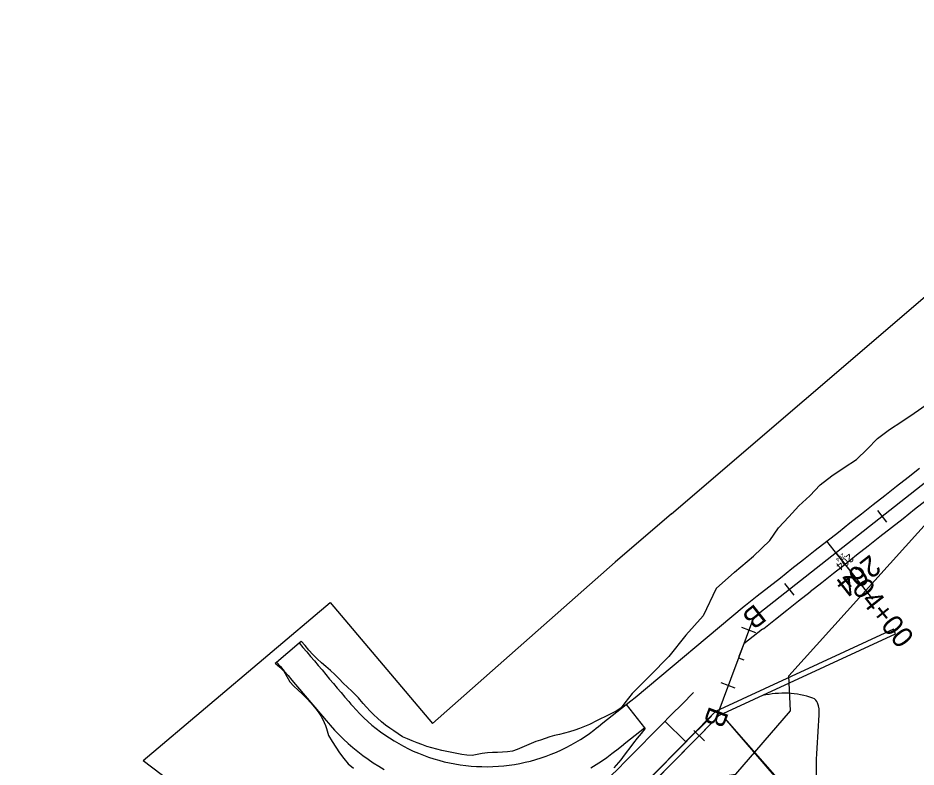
# Model space of a CAD drawing. Extents: x 1823824 to 1861612, y 706975 to 726130.
# Drawn here: x 1824837.5 to 1825141.5, y 712255.1 to 712508.6 of the extents above; entities that cross this region are included whole.
import ezdxf

# ---------------------------------------------------------------- set-up
doc = ezdxf.new("R2010")
doc.units = 0
for name, color, linetype in [('DR_X_Flood_Boundary', 7, 'Continuous'), ('GE_X_CL_10', 7, 'Continuous'), ('GE_X_CL_100', 7, 'Continuous'), ('GE_X_CL_20', 7, 'Continuous'), ('GE_X_CL_200', 7, 'Continuous'), ('GE_X_CL_50', 7, 'Continuous'), ('RW_X_Esmt_FL', 7, 'Continuous'), ('SC_Scratch1', 7, 'Continuous'), ('SC_Scratch2', 7, 'Continuous'), ('SC_Scratch3', 7, 'Continuous'), ('SC_Scratch5', 7, 'Continuous'), ('SC_Scratch6', 7, 'Continuous')]:
    doc.layers.add(name, color=color, linetype=linetype)

msp = doc.modelspace()

# ---------------------------------------------------------------- linework, layer by layer
at = {"layer": 'DR_X_Flood_Boundary'}
for p, q in [((1825243.83, 712429.46), (1825086.51, 712305.67)), ((1825086.51, 712305.67), (1825073.72, 712271.49)), ((1825073.72, 712271.49), (1825010.26, 712206.92))]:
    msp.add_line(p, q, dxfattribs=at)
at = {"layer": 'GE_X_CL_10'}
for p, q in [((1825114.42, 712327.63), (1825115.03, 712326.84)), ((1825081.43, 712292.1), (1825082.37, 712291.75))]:
    msp.add_line(p, q, dxfattribs=at)
at = {"layer": 'GE_X_CL_100'}
msp.add_line((1825114.42, 712327.63), (1825120.6, 712319.77), dxfattribs=at)
at = {"layer": 'GE_X_CL_20'}
for p, q in [((1825114.42, 712327.63), (1825115.65, 712326.06)), ((1825081.43, 712292.1), (1825083.3, 712291.4))]:
    msp.add_line(p, q, dxfattribs=at)
at = {"layer": 'GE_X_CL_200'}
msp.add_line((1825114.42, 712327.63), (1825126.78, 712311.91), dxfattribs=at)
at = {"layer": 'GE_X_CL_50'}
msp.add_line((1825114.42, 712327.63), (1825117.51, 712323.7), dxfattribs=at)
at = {"layer": 'RW_X_Esmt_FL'}
for p, q in [((1825058.79, 712340.8), (1825254.52, 712508.57)), ((1825058.79, 712340.8), (1825039.75, 712324.4)), ((1824977.83, 712269.92), (1825039.75, 712324.4)), ((1824879.92, 712257.3), (1824943.2, 712310.84)), ((1824943.2, 712310.84), (1824977.83, 712269.92)), ((1824879.92, 712257.3), (1824889.34, 712250.21))]:
    msp.add_line(p, q, dxfattribs=at)
at = {"layer": 'SC_Scratch1'}
for p, q in [((1825073.85, 712315.5), (1825080.12, 712321.03)), ((1825046.47, 712278.7), (1825083.42, 712309.6)), ((1825089.6, 712301.74), (1825083.21, 712296.86)), ((1825083.21, 712296.86), (1825081.59, 712292.52)), ((1825076.76, 712271.73), (1825133.34, 712206.03))]:
    msp.add_line(p, q, dxfattribs=at)
for points in [[(1824837.54, 711922.74), (1824848.43, 711918.74), (1824860.1, 711923.16), (1824873.6, 711947.64), (1824870.6, 711959.21), (1824893.22, 711999.63), (1824920.18, 712044.82), (1824961.46, 712108.81), (1824989.89, 712150.42), (1824991.25, 712152.45), (1825003.05, 712154.01), (1825020.13, 712176.93), (1825019.11, 712188.57), (1825068.43, 712250.92), (1825080.52, 712252.77), (1825099.08, 712274.14), (1825098.5, 712286.03), (1825161.91, 712356.25)], [(1824837.54, 711922.74), (1824848.43, 711918.74), (1824860.1, 711923.16), (1824873.6, 711947.64), (1824870.6, 711959.21), (1824893.22, 711999.63), (1824920.18, 712044.82), (1824961.46, 712108.81), (1824989.89, 712150.42), (1824991.25, 712152.45), (1825003.05, 712154.01), (1825020.13, 712176.93), (1825019.11, 712188.57), (1825068.43, 712250.92), (1825080.52, 712252.77), (1825099.08, 712274.14), (1825098.5, 712286.03), (1825161.91, 712356.25)], [(1825080.12, 712321.03), (1825086.51, 712326.48), (1825092.08, 712331.76)], [(1825083.42, 712309.6), (1825083.82, 712309.91), (1825087.75, 712313.01), (1825091.68, 712316.1), (1825095.61, 712319.19), (1825099.53, 712322.28), (1825099.53, 712322.28)], [(1825073.85, 712315.5), (1825069.48, 712306.35), (1825063.64, 712299.71), (1825057.83, 712292.56), (1825051.5, 712286.15), (1825047.36, 712281.96), (1825045.42, 712280.04)], [(1825089.6, 712301.74), (1825090, 712302.05), (1825093.93, 712305.15), (1825097.86, 712308.24), (1825101.79, 712311.33), (1825105.72, 712314.42), (1825105.72, 712314.42)], [(1824924.59, 712290.24), (1824925.07, 712290.65), (1824932.7, 712297.12), (1824933.43, 712297.74)], [(1824932.7, 712297.12), (1824933.99, 712295.6), (1824935.29, 712294.07), (1824936.58, 712292.55), (1824937.87, 712291.02), (1824939.17, 712289.5), (1824940.46, 712287.97), (1824941.76, 712286.45), (1824943.05, 712284.92), (1824944.34, 712283.4), (1824945.64, 712281.87), (1824946.93, 712280.35), (1824948.23, 712278.82), (1824949.52, 712277.3), (1824950.25, 712276.44), (1824950.78, 712275.83), (1824952.01, 712274.46), (1824953.29, 712273.12), (1824954.6, 712271.83), (1824955.96, 712270.57), (1824957.35, 712269.36), (1824958.78, 712268.2), (1824960.25, 712267.07), (1824961.75, 712266), (1824963.28, 712264.97), (1824964.84, 712263.98), (1824966.43, 712263.05), (1824968.05, 712262.16), (1824969.7, 712261.33), (1824971.37, 712260.54), (1824973.07, 712259.81), (1824974.78, 712259.13), (1824976.52, 712258.51), (1824978.27, 712257.93), (1824980.05, 712257.42), (1824981.83, 712256.95), (1824983.63, 712256.54), (1824985.45, 712256.19), (1824987.27, 712255.89), (1824989.1, 712255.65), (1824990.93, 712255.47), (1824992.78, 712255.34), (1824994.62, 712255.27), (1824996.47, 712255.26), (1824998.31, 712255.3), (1825000.16, 712255.4), (1825002, 712255.56), (1825003.83, 712255.77), (1825005.66, 712256.04), (1825007.47, 712256.36), (1825009.28, 712256.74), (1825011.07, 712257.18), (1825012.85, 712257.67), (1825014.62, 712258.22), (1825016.36, 712258.82), (1825018.09, 712259.47), (1825019.79, 712260.17), (1825021.48, 712260.93), (1825023.14, 712261.74), (1825024.77, 712262.6), (1825026.38, 712263.51), (1825027.95, 712264.47), (1825029.5, 712265.48), (1825031.02, 712266.53), (1825032.5, 712267.63), (1825033.28, 712268.24), (1825034.01, 712268.82), (1825035.57, 712270.06), (1825037.14, 712271.3), (1825038.71, 712272.54), (1825040.28, 712273.79), (1825041.84, 712275.03), (1825043.41, 712276.27), (1825044.98, 712277.51), (1825046.47, 712278.7)], [(1825045.42, 712280.04), (1825044.22, 712278.47), (1825042.98, 712276.82), (1825041.75, 712275.15), (1825040.09, 712274.02), (1825038.25, 712273.13), (1825036.39, 712272.25), (1825034.54, 712271.37), (1825032.74, 712270.42), (1825031.9, 712269.98), (1825031.02, 712269.56), (1825029.36, 712268.83), (1825027.68, 712268.19), (1825025.99, 712267.6), (1825024.29, 712267.06), (1825022.6, 712266.58), (1825020.9, 712266.15), (1825019.21, 712265.78), (1825017.54, 712265.39), (1825015.97, 712264.82), (1825014.4, 712264.26), (1825012.81, 712263.74), (1825011.27, 712263.08), (1825009.72, 712262.39), (1825008.15, 712261.72), (1825006.56, 712261.07), (1825004.93, 712260.48), (1825003.23, 712260.33), (1825001.53, 712260.21), (1824999.83, 712260.11), (1824998.13, 712260.02), (1824996.43, 712259.96), (1824994.72, 712259.67), (1824992.99, 712259.33), (1824991.24, 712259.02), (1824989.5, 712259.16), (1824987.78, 712259.41), (1824986.07, 712259.7), (1824984.36, 712260.02), (1824982.66, 712260.37), (1824980.97, 712260.76), (1824979.28, 712261.18), (1824977.59, 712261.63), (1824975.91, 712262.12), (1824974.27, 712262.71), (1824972.62, 712263.33), (1824970.99, 712263.98), (1824969.37, 712264.67), (1824967.76, 712265.39), (1824966.27, 712266.34), (1824964.82, 712267.34), (1824963.38, 712268.34), (1824961.95, 712269.36), (1824960.57, 712270.46), (1824959.26, 712271.63), (1824957.99, 712272.84), (1824956.76, 712274.09), (1824955.56, 712275.37), (1824954.41, 712276.68), (1824953.27, 712278), (1824952.76, 712278.56), (1824951.98, 712279.39), (1824950.6, 712280.84), (1824949.1, 712282.18), (1824947.61, 712283.54), (1824946.22, 712284.99), (1824944.83, 712286.43), (1824943.32, 712287.78), (1824941.8, 712289.11), (1824940.29, 712290.45), (1824938.78, 712291.79), (1824937.35, 712293.2), (1824935.95, 712294.64), (1824934.71, 712296.21), (1824933.43, 712297.74)], [(1824924.59, 712290.24), (1824926.18, 712288.97), (1824927.56, 712287.52), (1824928.59, 712285.77), (1824929.62, 712284.02), (1824930.97, 712282.54), (1824932.41, 712281.14), (1824933.86, 712279.75), (1824935.28, 712278.33), (1824936.69, 712276.91), (1824937.95, 712275.35), (1824939.17, 712273.76), (1824940.33, 712272.13), (1824941.14, 712270.18), (1824941.67, 712269.15), (1824941.99, 712268.17), (1824942.64, 712265.77), (1824943.86, 712263.83), (1824945.13, 712261.89), (1824946.39, 712259.9), (1824947.83, 712258.06), (1824949.3, 712256.21), (1824951.08, 712254.72)], [(1824925.07, 712290.65), (1824926.37, 712289.13), (1824927.66, 712287.6), (1824928.96, 712286.08), (1824930.25, 712284.55), (1824931.54, 712283.03), (1824932.84, 712281.5), (1824934.13, 712279.98), (1824935.43, 712278.45), (1824936.72, 712276.93), (1824938.01, 712275.4), (1824939.31, 712273.88), (1824940.6, 712272.35), (1824941.9, 712270.83), (1824942.63, 712269.97), (1824943.24, 712269.26), (1824944.68, 712267.66), (1824946.17, 712266.1), (1824947.7, 712264.59), (1824949.28, 712263.13), (1824950.91, 712261.71), (1824952.58, 712260.35), (1824954.29, 712259.04), (1824956.04, 712257.79), (1824957.82, 712256.58), (1824959.65, 712255.44), (1824961.5, 712254.35)], [(1825066.18, 712280.36), (1825062.33, 712276.46), (1825058.81, 712272.91), (1825055.29, 712269.35), (1825051.78, 712265.8), (1825048.26, 712262.24), (1825044.75, 712258.69), (1825042.54, 712256.46), (1825041.23, 712255.12), (1825037.72, 712251.56), (1825034.21, 712248), (1825030.7, 712244.43), (1825027.19, 712240.87), (1825023.69, 712237.31), (1825020.18, 712233.74), (1825016.67, 712230.18), (1825013.16, 712226.62), (1825009.65, 712223.06), (1825006.15, 712219.49), (1825002.64, 712215.93), (1825001.15, 712214.42)], [(1825043.41, 712276.27), (1825049.62, 712268.44), (1825049.87, 712268.12)], [(1825076.76, 712271.73), (1825103.98, 712240.57), (1825107.47, 712236.43), (1825119.63, 712222.05)], [(1825031.44, 712254.89), (1825033.28, 712256.01), (1825035.08, 712257.18), (1825036.85, 712258.41), (1825038.58, 712259.7), (1825039.49, 712260.4), (1825040.22, 712260.98), (1825041.79, 712262.22), (1825043.35, 712263.47), (1825044.92, 712264.71), (1825046.49, 712265.95), (1825048.06, 712267.19), (1825049.62, 712268.44), (1825049.62, 712268.44)], [(1825039.38, 712254.89), (1825040.92, 712256.65), (1825041.7, 712257.61), (1825042.29, 712258.37), (1825043.54, 712260.02), (1825044.78, 712261.66), (1825046.03, 712263.3), (1825047.3, 712264.92), (1825048.59, 712266.52), (1825049.87, 712268.12)], [(1825063.57, 712263.66), (1825056.54, 712270.61)]]:
    msp.add_lwpolyline(points, dxfattribs=at)
for centre, radius, start, end in [((1825096.65, 712249.59), 30.53, 70.9134, 103.2382), ((1825105.78, 712275.99), 2.59, 18.9083, 70.9134), ((1825098.27, 712273.41), 10.54, 356.6894, 18.9083), ((1824155.54, 712327.94), 954.84, 355.7851, 356.68942), ((1824999.17, 712252.81), 108.74, 354.2399, 2.6127)]:
    msp.add_arc(centre, radius, start, end, dxfattribs=at)
at = {"layer": 'SC_Scratch2'}
for points in [[(1825092.08, 712331.76), (1825095.02, 712336.11), (1825098.46, 712339.82), (1825101.9, 712343.53), (1825105.59, 712346.93), (1825109.05, 712350.62), (1825113.03, 712353.65), (1825117.2, 712356.43), (1825121.37, 712359.21), (1825125.05, 712362.63), (1825128.55, 712366.26), (1825132.52, 712369.3), (1825136.69, 712372.09), (1825140.86, 712374.87), (1825145.03, 712377.66)], [(1825099.53, 712322.28), (1825103.46, 712325.37), (1825107.39, 712328.47), (1825111.32, 712331.56), (1825115.25, 712334.65), (1825119.18, 712337.74), (1825123.11, 712340.83), (1825127.04, 712343.93), (1825130.97, 712347.02), (1825134.9, 712350.11), (1825138.83, 712353.2), (1825142.76, 712356.29)], [(1825145.01, 712345.34), (1825141.08, 712342.25), (1825137.15, 712339.16), (1825133.22, 712336.07), (1825129.29, 712332.97), (1825125.37, 712329.88), (1825121.44, 712326.79), (1825117.51, 712323.7), (1825113.58, 712320.61), (1825109.65, 712317.51), (1825105.72, 712314.42)]]:
    msp.add_lwpolyline(points, dxfattribs=at)
at = {"layer": 'SC_Scratch3'}
for points in [[(1825010.26, 712206.92), (1825073.72, 712271.49), (1825074.74, 712272.54), (1825134.63, 712300.18), (1825133.92, 712301.78), (1825073.7, 712273.96), (1825072.21, 712272.45), (1825008.3, 712207.43)], [(1825072.32, 712272.35), (1825069.44, 712269.43), (1825065.92, 712265.88), (1825062.4, 712262.32), (1825058.89, 712258.77), (1825055.37, 712255.21), (1825051.86, 712251.66), (1825049.65, 712249.42), (1825048.35, 712248.11), (1825044.84, 712244.54), (1825041.34, 712240.98), (1825037.83, 712237.42), (1825034.32, 712233.85), (1825030.81, 712230.29), (1825027.3, 712226.73), (1825023.8, 712223.17), (1825020.29, 712219.6), (1825016.78, 712216.04), (1825013.27, 712212.48), (1825009.76, 712208.91), (1825008.3, 712207.43)]]:
    msp.add_lwpolyline(points, dxfattribs=at)
at = {"layer": 'SC_Scratch5'}
for points in [[(1825131.68, 712338.03), (1825128.59, 712341.96)], [(1825117.51, 712323.7), (1825111.32, 712331.56)], [(1825100.24, 712313.3), (1825097.15, 712317.23)], [(1825087.28, 712300.59), (1825082.59, 712302.34)], [(1825080.27, 712281.86), (1825075.59, 712283.61)], [(1825069.9, 712264.03), (1825066.33, 712267.54)]]:
    msp.add_lwpolyline(points, dxfattribs=at)

# ---------------------------------------------------------------- texts
at = {"layer": 'GE_X_CL_10'}
msp.add_text('204', height=1.4, rotation=218.1993, dxfattribs=at).set_placement((1825116.75, 712327.55))
at = {"layer": 'GE_X_CL_20'}
msp.add_text('204', height=2.8, rotation=218.1993, dxfattribs=at).set_placement((1825119.08, 712327.48))
at = {"layer": 'GE_X_CL_50'}
msp.add_text('204', height=7, rotation=218.1993, dxfattribs=at).set_placement((1825126.07, 712327.26))
at = {"layer": 'SC_Scratch5'}
msp.add_text('204+00', height=7, rotation=308.1993, dxfattribs=at).set_placement((1825116.3, 712319.57))
at = {"layer": 'SC_Scratch6'}
for rotation, p in [(218.1993, (1825087.09, 712310.58)), (249.4879, (1825071.67, 712275.99))]:
    msp.add_text('B', height=7, rotation=rotation, dxfattribs=at).set_placement(p)

doc.saveas('drawing.dxf')
